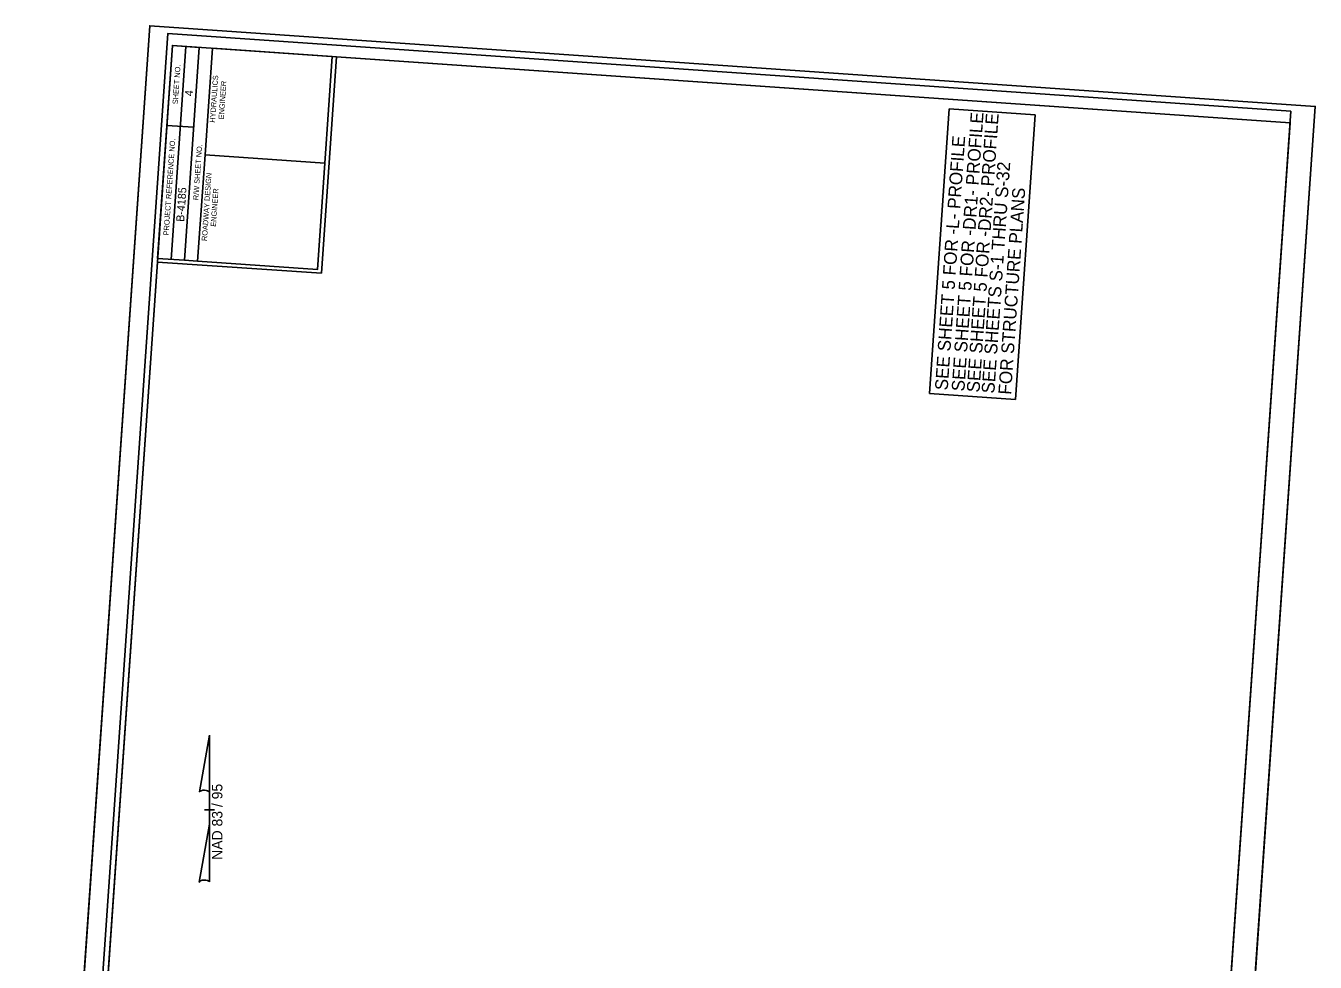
# Model space of a CAD drawing. Extents: x 2598940 to 2600149, y 728414 to 730169.
# Drawn here: x 2598940 to 2600149, y 729291 to 730169 of the extents above; entities that cross this region are included whole.
import ezdxf

# ---------------------------------------------------------------- set-up
doc = ezdxf.new("R2010")
doc.units = 0
for name, color, linetype in [('Default', 7, 'Continuous'), ('Prop Dimension Text', 7, 'Continuous'), ('Sheet Clip Boundary CELL', 7, 'Continuous'), ('Sheet Cutting Line CELL', 7, 'Continuous'), ('Sheet Data Field CELL', 7, 'Continuous'), ('Sheet Plan CELL', 7, 'Continuous'), ('Sheet Plot Border Inside CELL', 7, 'Continuous'), ('Sheet Plot Border Outside CELL', 7, 'Continuous')]:
    doc.layers.add(name, color=color, linetype=linetype)

msp = doc.modelspace()

# ---------------------------------------------------------------- linework, layer by layer
at = {"layer": 'Default'}
for p, q in [((2599787.5, 729824), (2599805.9, 730090.9)), ((2599805.9, 730090.9), (2599886.5, 730085.3)), ((2599868.1, 729818.5), (2599886.5, 730085.3)), ((2599787.5, 729824), (2599868.1, 729818.5))]:
    msp.add_line(p, q, dxfattribs=at)
at = {"layer": 'Sheet Clip Boundary CELL'}
for p, q in [((2599231.5, 730139.5), (2599217.5, 729936.7)), ((2600125.3, 730077.7), (2599231.5, 730139.5)), ((2600021.7, 728581.2), (2600125.3, 730077.7)), ((2599063.7, 729947.3), (2598974.2, 728653.7)), ((2599217.5, 729936.7), (2599063.7, 729947.3))]:
    msp.add_line(p, q, dxfattribs=at)
at = {"layer": 'Sheet Cutting Line CELL'}
for p, q in [((2599056.5, 730168.7), (2598940.3, 728489.2)), ((2600032.7, 728413.6), (2600148.9, 730093.1)), ((2599103, 729450.7), (2599112.4, 729504)), ((2599112.5, 729504), (2599112.4, 729504)), ((2599112.5, 729504), (2599112.4, 729504)), ((2599112.5, 729504), (2599112.5, 729449)), ((2599112.5, 729420.5), (2599112.5, 729450.6)), ((2599112.5, 729449), (2599112.5, 729450.5)), ((2599107.9, 729433.8), (2599107.8, 729433.8)), ((2599107.9, 729433.8), (2599117.1, 729433.8)), ((2599111.9, 729433.8), (2599107.9, 729433.8)), ((2599112.5, 729420.5), (2599102.8, 729366.1)), ((2599112.5, 729366.3), (2599112.5, 729420.5))]:
    msp.add_line(p, q, dxfattribs=at)
for centre, start_param, end_param in [((2599107.7, 729450.1), 0.216388, 2.908219), ((2599107.7, 729365.9), 0.201328, 3.141593)]:
    msp.add_ellipse(centre, major_axis=(4.87, -0.03), ratio=0.461098, start_param=start_param, end_param=end_param, dxfattribs=at)
at = {"layer": 'Sheet Plan CELL'}
for p, q in [((2599076.5, 729949.7), (2599090.3, 730149.3)), ((2599089, 729948.9), (2599102.8, 730148.4)), ((2599089, 729948.9), (2599102.8, 730148.4)), ((2599072.6, 730075.3), (2599097.6, 730073.6)), ((2599089, 729948.9), (2599101.4, 729948))]:
    msp.add_line(p, q, dxfattribs=at)
for points in [[(2599077.8, 730150.2), (2598974.2, 728653.7), (2600021.7, 728581.2), (2600125.3, 730077.7)], [(2599063.9, 729950.6), (2599077.8, 730150.2), (2599102.8, 730148.4), (2599089, 729948.9)], [(2599108.3, 730047.8), (2599115.2, 730147.6), (2599227.5, 730139.8), (2599220.6, 730040)], [(2599101.4, 729948), (2599108.3, 730047.8), (2599220.6, 730040), (2599213.7, 729940.2)]]:
    msp.add_lwpolyline(points, close=True, dxfattribs=at)
at = {"layer": 'Sheet Plot Border Inside CELL'}
msp.add_lwpolyline([(2600011, 728426.6), (2600126, 730088.6), (2599073.5, 730161.5), (2598958.5, 728499.4)], close=True, dxfattribs=at)
at = {"layer": 'Sheet Plot Border Outside CELL'}
msp.add_lwpolyline([(2600032.7, 728413.6), (2600148.9, 730093.1), (2599056.5, 730168.7), (2598940.3, 728489.2)], close=True, dxfattribs=at)

# ---------------------------------------------------------------- texts
at = {"layer": 'Prop Dimension Text'}
for s, p in [('SEE SHEET 5 FOR -DR1- PROFILE', (2599820, 729825.8)), ('SEE SHEET 5 FOR -DR2- PROFILE', (2599834.2, 729824.8)), ('SEE SHEET 5 FOR -L- PROFILE', (2599804.4, 729826.8)), ('SEE SHEETS S-1 THRU S-32 ', (2599848.1, 729823.8)), ('FOR STRUCTURE PLANS', (2599863.8, 729822.7))]:
    msp.add_text(s, height=12, rotation=86.0422, dxfattribs=at).set_placement(p)
at = {"layer": 'Sheet Cutting Line CELL'}
msp.add_text('NAD 83 / 95', height=9.777, rotation=90, dxfattribs=at).set_placement((2599124.6, 729387.1))
at = {"layer": 'Sheet Data Field CELL'}
for s, p in [('4  ', (2599096.8, 730102.5)), ('B-4185   ', (2599088.7, 729984.8))]:
    msp.add_text(s, height=7.5, rotation=86.0423, dxfattribs=at).set_placement(p)
at = {"layer": 'Sheet Plan CELL'}
for s, p in [('SHEET NO.', (2599082.8, 730095)), ('HYDRAULICS', (2599117.7, 730077.7)), ('ENGINEER', (2599125.9, 730080.9)), ('PROJECT REFERENCE NO.', (2599074.2, 729972.1)), ('R/W SHEET NO.', (2599102.1, 730005.1)), ('ROADWAY DESIGN', (2599110.1, 729966.8)), ('ENGINEER', (2599118.5, 729980.2))]:
    msp.add_text(s, height=5, rotation=86.0423, dxfattribs=at).set_placement(p)

doc.saveas('drawing.dxf')
